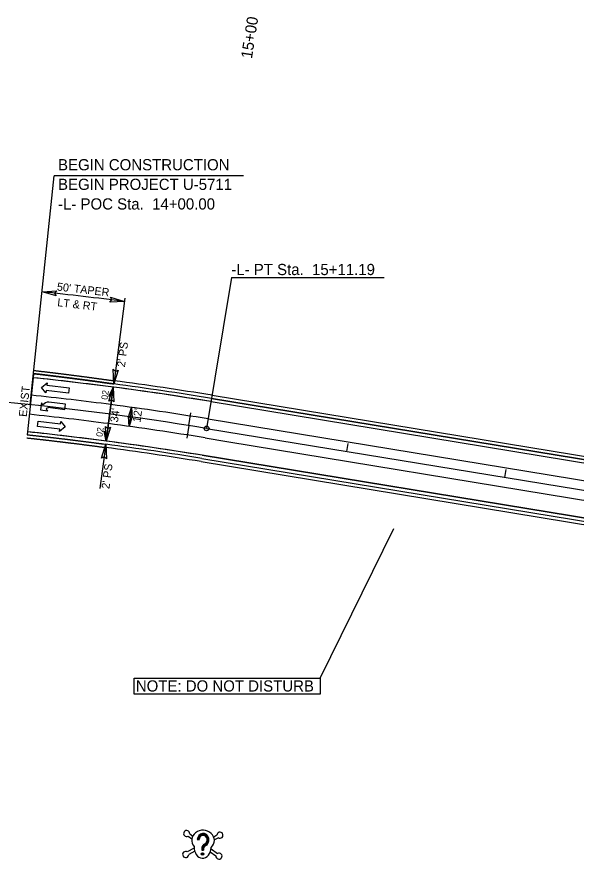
# Model space of a CAD drawing. Extents: x 1755545 to 1761252, y 736169 to 737766.
# Drawn here: x 1756089 to 1756439, y 736862 to 737388 of the extents above; entities that cross this region are included whole.
import ezdxf

# ---------------------------------------------------------------- set-up
doc = ezdxf.new("R2010")
doc.units = 0
for name, color, linetype in [('Default', 7, 'Continuous'), ('Exist Contamination Potential Cell', 7, 'Continuous'), ('Exist Cultural Church Label', 7, 'Continuous'), ('Prop Dimension', 7, 'Continuous'), ('Prop Horizontal Alignment', 7, 'Continuous'), ('Prop Horizontal Alignment Station Label', 7, 'Continuous'), ('Prop Horizontal Alignment Tick Label', 7, 'Continuous'), ('Prop Horizontal Alignment Tick Large', 7, 'Continuous'), ('Prop Horizontal Alignment Tick Small', 7, 'Continuous'), ('Prop Lane Arrow CELL', 7, 'Continuous'), ('Prop Lane Lines', 7, 'Continuous'), ('Prop Paved Shoulder', 7, 'Continuous'), ('Prop Shade Light', 7, 'Continuous'), ('Prop Superelevation Label', 7, 'Continuous'), ('Prop Terminator CELL', 7, 'Continuous'), ('Scratch_Level_6', 7, 'Continuous')]:
    doc.layers.add(name, color=color, linetype=linetype)

msp = doc.modelspace()

# ---------------------------------------------------------------- linework, layer by layer
at = {"layer": 'Default'}
for p, q in [((1756196.18, 736875.91), (1756198.51, 736874.29)), ((1756197.21, 736877.37), (1756199.08, 736876.06)), ((1756201.89, 736873.79), (1756203.03, 736873.74)), ((1756214.24, 736876.55), (1756212.25, 736875.42)), ((1756215.12, 736874.99), (1756212.65, 736873.6)), ((1756200.02, 736868.54), (1756195.71, 736866.11)), ((1756204.74, 736868.3), (1756204.69, 736867.3)), ((1756204.9, 736868.29), (1756204.85, 736867.29)), ((1756205.06, 736868.28), (1756205.01, 736867.29)), ((1756205.22, 736868.27), (1756205.17, 736867.28)), ((1756205.38, 736868.26), (1756205.34, 736867.27)), ((1756205.44, 736871.13), (1756205.44, 736871.13)), ((1756205.55, 736868.26), (1756205.5, 736867.26)), ((1756205.71, 736868.25), (1756205.66, 736867.25)), ((1756205.87, 736868.24), (1756205.82, 736867.25)), ((1756210.59, 736868.03), (1756214.64, 736865.2)), ((1756200.33, 736866.67), (1756196.58, 736864.56)), ((1756204.69, 736867.3), (1756205.82, 736867.25)), ((1756210.1, 736866.2), (1756213.62, 736863.74))]:
    msp.add_line(p, q, dxfattribs=at)
for radius in [0.81, 0.63, 0.446, 0.266, 0.0863]:
    msp.add_circle((1756205.18, 736864.81), radius, dxfattribs=at)
for centre, start, end in [((1756195.32, 736877.6), 353.1242, 297.0327), ((1756216.14, 736876.59), 237.4204, 181.3289), ((1756194.69, 736864.52), 57.4204, 1.3289), ((1756215.5, 736863.51), 173.1242, 117.0327)]:
    msp.add_arc(centre, 1.9, start, end, dxfattribs=at)
for centre, major_axis, ratio, start_param, end_param in [((1756205.55, 736873.38), (7.1, -0.34), 0.885014, 5.564242, 10.143721), ((1756205.56, 736873.62), (0.2, 4.08), 0.9, 3.567618, 7.853982), ((1756205.56, 736873.62), (0.19, 3.9), 0.9, 3.567618, 7.853982), ((1756205.56, 736873.62), (0.18, 3.72), 0.9, 3.567618, 7.853982), ((1756205.56, 736873.62), (0.17, 3.54), 0.9, 3.567618, 7.853982), ((1756205.56, 736873.62), (0.16, 3.36), 0.9, 3.567618, 7.853982), ((1756205.56, 736873.62), (0.15, 3.18), 0.9, 3.567618, 7.853982), ((1756205.56, 736873.62), (0.15, 3), 0.9, 3.567618, 7.853982), ((1756205.56, 736873.62), (0.14, 2.82), 0.9, 3.567618, 7.853982), ((1756205.35, 736869.31), (-0.34, -7.1), 0.752542, 4.722735, 7.843636), ((1756207.49, 736868.16), (0.15, 3.06), 0.9, 0.426026, 1.570796), ((1756207.49, 736868.16), (0.14, 2.88), 0.9, 0.426026, 1.570796), ((1756207.49, 736868.16), (0.13, 2.7), 0.9, 0.426026, 1.570796), ((1756207.49, 736868.16), (0.12, 2.52), 0.9, 0.426026, 1.570796), ((1756207.49, 736868.16), (0.11, 2.34), 0.9, 0.426026, 1.570796), ((1756207.49, 736868.16), (0.1, 2.16), 0.9, 0.426026, 1.570796), ((1756207.49, 736868.16), (0.1, 1.98), 0.9, 0.426026, 1.570796), ((1756207.49, 736868.16), (0.09, 1.8), 0.9, 0.426026, 1.570796)]:
    msp.add_ellipse(centre, major_axis=major_axis, ratio=ratio, start_param=start_param, end_param=end_param, dxfattribs=at)
at = {"layer": 'Exist Contamination Potential Cell'}
for p, q in [((1756099.36, 737162.36), (1756095.83, 737128.54)), ((1756210.53, 737147.44), (1756991.88, 737019.17)), ((1756205.02, 737113.89), (1756986.38, 736985.62))]:
    msp.add_line(p, q, dxfattribs=at)
for radius, start, end in [(1914, 82.52564, 84.03581), (1914, 80.67753, 82.52564), (1880, 82.52564, 84.03581), (1880, 80.67753, 82.52564)]:
    msp.add_arc((1755900.48, 735258.72), radius, start, end, dxfattribs=at)
at = {"layer": 'Exist Cultural Church Label'}
for points in [[(1756149.46, 737156.46), (1756146.7, 737150.77), (1756148.86, 737151.87)], [(1756145.04, 737122.75), (1756143.83, 737128.96), (1756145.64, 737127.33)]]:
    msp.add_lwpolyline(points, close=True, dxfattribs=at)
at = {"layer": 'Prop Dimension'}
for p, q in [((1756156.74, 737211.98), (1756149.72, 737158.44)), ((1756149.46, 737156.46), (1756145.04, 737122.75)), ((1756160.95, 737143.81), (1756159.31, 737131.93)), ((1756144.78, 737120.76), (1756141.15, 737093.13)), ((1756278.67, 736974.59), (1756324.72, 737068.14))]:
    msp.add_line(p, q, dxfattribs=at)
msp.add_lwpolyline([(1756162.44, 736974.59), (1756278.67, 736974.59), (1756278.67, 736964.66), (1756162.44, 736964.66)], close=True, dxfattribs=at)
msp.add_arc((1755900.48, 735258.72), 1967.9, 82.52564, 84.03581, dxfattribs=at)
at = {"layer": 'Prop Horizontal Alignment'}
msp.add_line((1756207.78, 737130.67), (1757104.78, 736983.41), dxfattribs=at)
msp.add_arc((1755900.48, 735258.72), 1897, 80.67753, 89.04302, dxfattribs=at)
at = {"layer": 'Prop Horizontal Alignment Station Label'}
for p, q in [((1756097.59, 737145.45), (1756112.54, 737288.49)), ((1756230.86, 737288.49), (1756112.54, 737288.49)), ((1756223.24, 737224.89), (1756207.78, 737130.67)), ((1756223.24, 737224.89), (1756318.63, 737224.89))]:
    msp.add_line(p, q, dxfattribs=at)
msp.add_circle((1756207.78, 737130.67), 1.5, dxfattribs=at)
at = {"layer": 'Prop Horizontal Alignment Tick Large'}
for q in [(1756197.98, 737140.35), (1756195.48, 737124.54)]:
    msp.add_line((1756196.73, 737132.45), q, dxfattribs=at)
at = {"layer": 'Prop Horizontal Alignment Tick Small'}
for p, q in [((1756097.59, 737145.45), (1756098.11, 737150.42)), ((1756295.42, 737116.28), (1756296.23, 737121.21)), ((1756394.09, 737100.08), (1756394.9, 737105.01))]:
    msp.add_line(p, q, dxfattribs=at)
at = {"layer": 'Prop Lane Arrow CELL'}
for p, q in [((1756104.64, 737156.33), (1756108.15, 737159.14)), ((1756108.15, 737159.14), (1756107.97, 737157.65)), ((1756107.97, 737157.65), (1756121.87, 737156.01)), ((1756107.41, 737152.88), (1756104.64, 737156.33)), ((1756107.58, 737154.37), (1756107.41, 737152.88)), ((1756121.49, 737152.73), (1756107.58, 737154.37)), ((1756121.87, 737156.01), (1756121.49, 737152.73)), ((1756119.66, 737145.86), (1756109.18, 737147.09)), ((1756104.59, 737146.57), (1756104.02, 737142.21)), ((1756104.02, 737142.21), (1756108.49, 737141.63)), ((1756105.51, 737145.41), (1756104.59, 737146.57)), ((1756108.49, 737141.63), (1756107.57, 737142.8)), ((1756110.18, 737143.65), (1756119.27, 737142.58)), ((1756119.27, 737142.58), (1756119.66, 737145.86)), ((1756102.15, 737131.93), (1756102.54, 737135.2)), ((1756116.05, 737130.29), (1756102.15, 737131.93)), ((1756102.54, 737135.2), (1756116.44, 737133.57)), ((1756119.38, 737131.61), (1756115.88, 737128.8)), ((1756116.44, 737133.57), (1756116.62, 737135.05)), ((1756116.62, 737135.05), (1756119.38, 737131.61)), ((1756115.88, 737128.8), (1756116.05, 737130.29))]:
    msp.add_line(p, q, dxfattribs=at)
for centre, radius, start, end in [((1756109.36, 737141.86), 5.25, 91.9568, 137.2685), ((1756109.79, 737140.42), 3.27, 83.2807, 132.9389)]:
    msp.add_arc(centre, radius, start, end, dxfattribs=at)
at = {"layer": 'Prop Lane Lines'}
for p, q in [((1756208.75, 737136.59), (1756990.1, 737008.32)), ((1756206.81, 737124.74), (1756220.43, 737122.51)), ((1756220.43, 737122.51), (1756988.16, 736996.48))]:
    msp.add_line(p, q, dxfattribs=at)
for radius, start, end in [(1903, 82.52564, 84.03581), (1903, 80.67753, 82.52564), (1891, 82.52564, 84.03581), (1891, 80.67753, 82.52564)]:
    msp.add_arc((1755900.48, 735258.72), radius, start, end, dxfattribs=at)
at = {"layer": 'Prop Paved Shoulder'}
for p, q in [((1756099.62, 737164.89), (1756099.36, 737162.36)), ((1756210.85, 737149.41), (1756992.21, 737021.15)), ((1756095.83, 737128.54), (1756095.64, 737126.74)), ((1756204.7, 737111.92), (1756986.05, 736983.65))]:
    msp.add_line(p, q, dxfattribs=at)
for radius in [1916, 1878]:
    msp.add_arc((1755900.48, 735258.72), radius, 80.67753, 82.52564, dxfattribs=at)
for points in [[(1756099.62, 737164.89), (1756100.3, 737164.82), (1756100.98, 737164.74), (1756101.66, 737164.66), (1756102.34, 737164.58), (1756103.01, 737164.5), (1756103.69, 737164.42), (1756104.37, 737164.34), (1756105.05, 737164.26), (1756105.73, 737164.18), (1756106.4, 737164.1), (1756107.08, 737164.02), (1756107.76, 737163.94), (1756108.44, 737163.86), (1756109.11, 737163.77), (1756109.79, 737163.69), (1756110.47, 737163.61), (1756111.15, 737163.53), (1756111.83, 737163.45), (1756112.5, 737163.36), (1756113.18, 737163.28), (1756113.86, 737163.2), (1756114.54, 737163.11), (1756115.21, 737163.03), (1756115.89, 737162.95), (1756116.57, 737162.86), (1756117.25, 737162.78), (1756117.92, 737162.69), (1756118.6, 737162.61), (1756119.28, 737162.52), (1756119.95, 737162.44), (1756120.63, 737162.35), (1756121.31, 737162.27), (1756121.99, 737162.18), (1756122.66, 737162.09), (1756123.34, 737162.01), (1756124.02, 737161.92), (1756124.69, 737161.83), (1756125.37, 737161.75), (1756126.05, 737161.66), (1756126.72, 737161.57), (1756127.4, 737161.48), (1756128.08, 737161.39), (1756128.76, 737161.3), (1756129.43, 737161.22), (1756130.11, 737161.13), (1756130.79, 737161.04), (1756131.46, 737160.95), (1756132.14, 737160.86), (1756132.82, 737160.77), (1756133.49, 737160.68), (1756134.17, 737160.59), (1756134.84, 737160.5), (1756135.52, 737160.41), (1756136.2, 737160.31), (1756136.87, 737160.22), (1756137.55, 737160.13), (1756138.23, 737160.04), (1756138.9, 737159.95), (1756139.58, 737159.86), (1756140.26, 737159.76), (1756140.93, 737159.67), (1756141.61, 737159.58), (1756142.28, 737159.48), (1756142.96, 737159.39), (1756143.64, 737159.3), (1756144.31, 737159.2), (1756144.99, 737159.11), (1756145.66, 737159.01), (1756146.34, 737158.92), (1756147.02, 737158.82), (1756147.69, 737158.73), (1756148.37, 737158.63), (1756149.72, 737158.44)], [(1756095.64, 737126.74), (1756096.3, 737126.67), (1756096.97, 737126.6), (1756097.63, 737126.52), (1756098.3, 737126.45), (1756098.96, 737126.38), (1756099.63, 737126.3), (1756100.29, 737126.23), (1756100.96, 737126.16), (1756101.62, 737126.08), (1756102.29, 737126.01), (1756102.95, 737125.93), (1756103.62, 737125.86), (1756104.28, 737125.78), (1756104.95, 737125.71), (1756105.61, 737125.63), (1756106.28, 737125.56), (1756106.94, 737125.48), (1756107.6, 737125.41), (1756108.27, 737125.33), (1756108.93, 737125.25), (1756109.6, 737125.18), (1756110.26, 737125.1), (1756110.93, 737125.02), (1756111.59, 737124.94), (1756112.26, 737124.87), (1756112.92, 737124.79), (1756113.58, 737124.71), (1756114.25, 737124.63), (1756114.91, 737124.55), (1756115.58, 737124.47), (1756116.24, 737124.39), (1756116.91, 737124.31), (1756117.57, 737124.23), (1756118.23, 737124.15), (1756118.9, 737124.07), (1756119.56, 737123.99), (1756120.23, 737123.91), (1756120.89, 737123.83), (1756121.55, 737123.75), (1756122.22, 737123.67), (1756122.88, 737123.59), (1756123.55, 737123.51), (1756124.21, 737123.42), (1756124.87, 737123.34), (1756125.54, 737123.26), (1756126.2, 737123.18), (1756126.87, 737123.09), (1756127.53, 737123.01), (1756128.19, 737122.93), (1756128.86, 737122.84), (1756129.52, 737122.76), (1756130.18, 737122.68), (1756130.85, 737122.59), (1756131.51, 737122.51), (1756132.17, 737122.42), (1756132.84, 737122.34), (1756133.5, 737122.25), (1756134.17, 737122.17), (1756134.83, 737122.08), (1756135.49, 737121.99), (1756136.16, 737121.91), (1756136.82, 737121.82), (1756137.48, 737121.73), (1756138.14, 737121.65), (1756138.81, 737121.56), (1756139.47, 737121.47), (1756140.13, 737121.38), (1756140.8, 737121.3), (1756141.46, 737121.21), (1756142.12, 737121.12), (1756142.79, 737121.03), (1756143.45, 737120.94), (1756144.78, 737120.76)]]:
    msp.add_spline(points, degree=3, dxfattribs=at)
at = {"layer": 'Prop Shade Light'}
for p, q in [((1756099.62, 737164.89), (1756099.36, 737162.36)), ((1756210.53, 737147.44), (1756991.88, 737019.17)), ((1756992.21, 737021.15), (1756210.85, 737149.41)), ((1756095.83, 737128.54), (1756095.64, 737126.74)), ((1756204.7, 737111.92), (1756986.05, 736983.65)), ((1756986.38, 736985.62), (1756205.02, 737113.89))]:
    msp.add_line(p, q, dxfattribs=at)
for radius, end in [(1914, 84.03581), (1916, 82.52564), (1880, 84.03581), (1878, 82.52564)]:
    msp.add_arc((1755900.48, 735258.72), radius, 80.67753, end, dxfattribs=at)
for points in [[(1756116.34, 737162.89), (1756115.89, 737162.95), (1756115.21, 737163.03), (1756114.54, 737163.11), (1756113.86, 737163.2), (1756113.18, 737163.28), (1756112.5, 737163.36), (1756111.83, 737163.45), (1756111.15, 737163.53), (1756110.47, 737163.61), (1756109.79, 737163.69), (1756109.11, 737163.77), (1756108.44, 737163.86), (1756107.76, 737163.94), (1756107.08, 737164.02), (1756106.4, 737164.1), (1756105.73, 737164.18), (1756105.05, 737164.26), (1756104.37, 737164.34), (1756103.69, 737164.42), (1756103.01, 737164.5), (1756102.34, 737164.58), (1756101.66, 737164.66), (1756100.98, 737164.74), (1756100.3, 737164.82), (1756099.62, 737164.89)], [(1756133.04, 737160.74), (1756132.82, 737160.77), (1756132.14, 737160.86), (1756131.46, 737160.95), (1756130.79, 737161.04), (1756130.11, 737161.13), (1756129.43, 737161.22), (1756128.76, 737161.3), (1756128.08, 737161.39), (1756127.4, 737161.48), (1756126.72, 737161.57), (1756126.05, 737161.66), (1756125.37, 737161.75), (1756124.69, 737161.83), (1756124.02, 737161.92), (1756123.34, 737162.01), (1756122.66, 737162.09), (1756121.99, 737162.18), (1756121.31, 737162.27), (1756120.63, 737162.35), (1756119.95, 737162.44), (1756119.28, 737162.52), (1756118.6, 737162.61), (1756117.92, 737162.69), (1756117.25, 737162.78), (1756116.57, 737162.86), (1756116.34, 737162.89)], [(1756149.72, 737158.44), (1756148.37, 737158.63), (1756147.69, 737158.73), (1756147.02, 737158.82), (1756146.34, 737158.92), (1756145.66, 737159.01), (1756144.99, 737159.11), (1756144.31, 737159.2), (1756143.64, 737159.3), (1756142.96, 737159.39), (1756142.28, 737159.48), (1756141.61, 737159.58), (1756140.93, 737159.67), (1756140.26, 737159.76), (1756139.58, 737159.86), (1756138.9, 737159.95), (1756138.23, 737160.04), (1756137.55, 737160.13), (1756136.87, 737160.22), (1756136.2, 737160.31), (1756135.52, 737160.41), (1756134.84, 737160.5), (1756134.17, 737160.59), (1756133.49, 737160.68), (1756133.04, 737160.74)], [(1756095.64, 737126.74), (1756096.3, 737126.67), (1756096.97, 737126.6), (1756097.63, 737126.52), (1756098.3, 737126.45), (1756098.96, 737126.38), (1756099.63, 737126.3), (1756100.29, 737126.23), (1756100.96, 737126.16), (1756101.62, 737126.08), (1756102.29, 737126.01), (1756102.95, 737125.93), (1756103.62, 737125.86), (1756104.28, 737125.78), (1756104.95, 737125.71), (1756105.61, 737125.63), (1756106.28, 737125.56), (1756106.94, 737125.48), (1756107.6, 737125.41), (1756108.27, 737125.33), (1756108.93, 737125.25), (1756109.6, 737125.18), (1756110.26, 737125.1), (1756110.93, 737125.02), (1756111.59, 737124.94), (1756112.03, 737124.89)], [(1756112.03, 737124.89), (1756112.26, 737124.87), (1756112.92, 737124.79), (1756113.58, 737124.71), (1756114.25, 737124.63), (1756114.91, 737124.55), (1756115.58, 737124.47), (1756116.24, 737124.39), (1756116.91, 737124.31), (1756117.57, 737124.23), (1756118.23, 737124.15), (1756118.9, 737124.07), (1756119.56, 737123.99), (1756120.23, 737123.91), (1756120.89, 737123.83), (1756121.55, 737123.75), (1756122.22, 737123.67), (1756122.88, 737123.59), (1756123.55, 737123.51), (1756124.21, 737123.42), (1756124.87, 737123.34), (1756125.54, 737123.26), (1756126.2, 737123.18), (1756126.87, 737123.09), (1756127.53, 737123.01), (1756128.19, 737122.93), (1756128.41, 737122.9)], [(1756128.41, 737122.9), (1756128.86, 737122.84), (1756129.52, 737122.76), (1756130.18, 737122.68), (1756130.85, 737122.59), (1756131.51, 737122.51), (1756132.17, 737122.42), (1756132.84, 737122.34), (1756133.5, 737122.25), (1756134.17, 737122.17), (1756134.83, 737122.08), (1756135.49, 737121.99), (1756136.16, 737121.91), (1756136.82, 737121.82), (1756137.48, 737121.73), (1756138.14, 737121.65), (1756138.81, 737121.56), (1756139.47, 737121.47), (1756140.13, 737121.38), (1756140.8, 737121.3), (1756141.46, 737121.21), (1756142.12, 737121.12), (1756142.79, 737121.03), (1756143.45, 737120.94), (1756144.78, 737120.76)]]:
    msp.add_spline(points, degree=3, dxfattribs=at)
at = {"layer": 'Prop Superelevation Label'}
msp.add_line((1756145.04, 737122.75), (1756149.46, 737156.46), dxfattribs=at)
at = {"layer": 'Prop Terminator CELL'}
for points in [[(1756113.75, 737213.5), (1756104.96, 737215.97), (1756114.13, 737216.63), (1756112.82, 737215.16)], [(1756147.74, 737212.59), (1756156.47, 737209.9), (1756147.29, 737209.48), (1756148.64, 737210.92)], [(1756152.43, 737167.16), (1756149.72, 737158.44), (1756149.31, 737167.62), (1756150.75, 737166.27)], [(1756146.75, 737147.74), (1756149.46, 737156.46), (1756149.87, 737147.28), (1756148.43, 737148.62)], [(1756159.02, 737137.72), (1756160.95, 737143.81), (1756161.19, 737137.38), (1756160.2, 737138.33)], [(1756161.25, 737138.02), (1756159.31, 737131.93), (1756159.07, 737138.35), (1756160.07, 737137.4)], [(1756147.74, 737131.47), (1756145.04, 737122.75), (1756144.63, 737131.93), (1756146.06, 737130.58)], [(1756142.07, 737112.04), (1756144.78, 737120.76), (1756145.18, 737111.58), (1756143.75, 737112.93)]]:
    msp.add_lwpolyline(points, close=True, dxfattribs=at)
at = {"layer": 'Scratch_Level_6'}
for p, q in [((1756211.18, 737151.39), (1756992.53, 737023.12)), ((1756204.38, 737109.94), (1756985.73, 736981.68))]:
    msp.add_line(p, q, dxfattribs=at)
for centre, radius, start, end in [((1755900.48, 735258.72), 1918, 80.67753, 82.52564), ((1755900.45, 735258.51), 1876.21, 80.67763, 82.52573)]:
    msp.add_arc(centre, radius, start, end, dxfattribs=at)
for points in [[(1756099.85, 737166.88), (1756100.53, 737166.8), (1756101.21, 737166.72), (1756101.89, 737166.65), (1756102.57, 737166.57), (1756103.25, 737166.49), (1756103.93, 737166.41), (1756104.6, 737166.33), (1756105.28, 737166.25), (1756105.96, 737166.17), (1756106.64, 737166.09), (1756107.32, 737166), (1756108, 737165.92), (1756108.68, 737165.84), (1756109.35, 737165.76), (1756110.03, 737165.68), (1756110.71, 737165.6), (1756111.39, 737165.51), (1756112.07, 737165.43), (1756112.75, 737165.35), (1756113.42, 737165.27), (1756114.1, 737165.18), (1756114.78, 737165.1), (1756115.46, 737165.01), (1756116.14, 737164.93), (1756116.81, 737164.85), (1756117.49, 737164.76), (1756118.17, 737164.68), (1756118.85, 737164.59), (1756119.53, 737164.51), (1756120.2, 737164.42), (1756120.88, 737164.34), (1756121.56, 737164.25), (1756122.24, 737164.16), (1756122.92, 737164.08), (1756123.59, 737163.99), (1756124.27, 737163.9), (1756124.95, 737163.82), (1756125.63, 737163.73), (1756126.3, 737163.64), (1756126.98, 737163.55), (1756127.66, 737163.46), (1756128.34, 737163.38), (1756129.02, 737163.29), (1756129.69, 737163.2), (1756130.37, 737163.11), (1756131.05, 737163.02), (1756131.72, 737162.93), (1756132.4, 737162.84), (1756133.08, 737162.75), (1756133.76, 737162.66), (1756134.43, 737162.57), (1756135.11, 737162.48), (1756135.79, 737162.39), (1756136.47, 737162.3), (1756137.14, 737162.21), (1756137.82, 737162.11), (1756138.5, 737162.02), (1756139.17, 737161.93), (1756139.85, 737161.84), (1756140.53, 737161.74), (1756141.2, 737161.65), (1756141.88, 737161.56), (1756142.56, 737161.46), (1756143.23, 737161.37), (1756143.91, 737161.28), (1756144.59, 737161.18), (1756145.26, 737161.09), (1756145.94, 737160.99), (1756146.62, 737160.9), (1756147.29, 737160.8), (1756147.97, 737160.71), (1756148.65, 737160.61), (1756150, 737160.42)], [(1756095.42, 737124.75), (1756096.09, 737124.68), (1756096.75, 737124.61), (1756097.41, 737124.53), (1756098.08, 737124.46), (1756098.74, 737124.39), (1756099.41, 737124.32), (1756100.07, 737124.24), (1756100.74, 737124.17), (1756101.4, 737124.09), (1756102.06, 737124.02), (1756102.73, 737123.95), (1756103.39, 737123.87), (1756104.06, 737123.8), (1756104.72, 737123.72), (1756105.38, 737123.65), (1756106.05, 737123.57), (1756106.71, 737123.49), (1756107.38, 737123.42), (1756108.04, 737123.34), (1756108.7, 737123.27), (1756109.37, 737123.19), (1756110.03, 737123.11), (1756110.7, 737123.03), (1756111.36, 737122.96), (1756112.02, 737122.88), (1756112.69, 737122.8), (1756113.35, 737122.72), (1756114.01, 737122.64), (1756114.68, 737122.57), (1756115.34, 737122.49), (1756116, 737122.41), (1756116.67, 737122.33), (1756117.33, 737122.25), (1756118, 737122.17), (1756118.66, 737122.09), (1756119.32, 737122.01), (1756119.99, 737121.93), (1756120.65, 737121.85), (1756121.31, 737121.77), (1756121.98, 737121.68), (1756122.64, 737121.6), (1756123.3, 737121.52), (1756123.96, 737121.44), (1756124.63, 737121.36), (1756125.29, 737121.28), (1756125.95, 737121.19), (1756126.62, 737121.11), (1756127.28, 737121.03), (1756127.94, 737120.94), (1756128.61, 737120.86), (1756129.27, 737120.78), (1756129.93, 737120.69), (1756130.59, 737120.61), (1756131.26, 737120.52), (1756131.92, 737120.44), (1756132.58, 737120.35), (1756133.25, 737120.27), (1756133.91, 737120.18), (1756134.57, 737120.1), (1756135.23, 737120.01), (1756135.9, 737119.92), (1756136.56, 737119.84), (1756137.22, 737119.75), (1756137.88, 737119.66), (1756138.55, 737119.58), (1756139.21, 737119.49), (1756139.87, 737119.4), (1756140.53, 737119.31), (1756141.2, 737119.23), (1756141.86, 737119.14), (1756142.52, 737119.05), (1756143.18, 737118.96), (1756144.51, 737118.78)]]:
    msp.add_spline(points, degree=3, dxfattribs=at)

# ---------------------------------------------------------------- texts
at = {"layer": 'Prop Dimension'}
for s, rotation, p in [("50' TAPER", 353.4433, (1756114.07, 737216.85)), ('LT & RT', 353.4433, (1756114.29, 737207.06)), ("2' PS", 82.5256, (1756156.69, 737168.71)), ('EXIST', 84.0712, (1756095.36, 737137.7)), ("34'", 82.5256, (1756152.36, 737134.24)), ("12'", 82.1532, (1756166.42, 737134.2)), ("2' PS", 82.5256, (1756147, 737092.66))]:
    msp.add_text(s, height=5, rotation=rotation, dxfattribs=at).set_placement(p)
msp.add_text('NOTE: DO NOT DISTURB ', height=7, dxfattribs=at).set_placement((1756163.56, 736966.31))
at = {"layer": 'Prop Horizontal Alignment Station Label'}
for s, p in [('BEGIN CONSTRUCTION', (1756114.95, 737291.9)), ('BEGIN PROJECT U-5711', (1756114.95, 737279.65)), ('-L- POC Sta.  14+00.00', (1756114.95, 737267.4)), ('-L- PT Sta.  15+11.19', (1756223.21, 737226.45))]:
    msp.add_text(s, height=7, rotation=360, dxfattribs=at).set_placement(p)
at = {"layer": 'Prop Horizontal Alignment Tick Label'}
msp.add_text('15+00', height=7, rotation=81.2065, dxfattribs=at).set_placement((1756236.09, 737361.33))
at = {"layer": 'Prop Superelevation Label'}
for p in [(1756145.89, 737148.4), (1756142.67, 737125.2)]:
    msp.add_text('02', height=4, rotation=82.5256, dxfattribs=at).set_placement(p)

doc.saveas('drawing.dxf')
